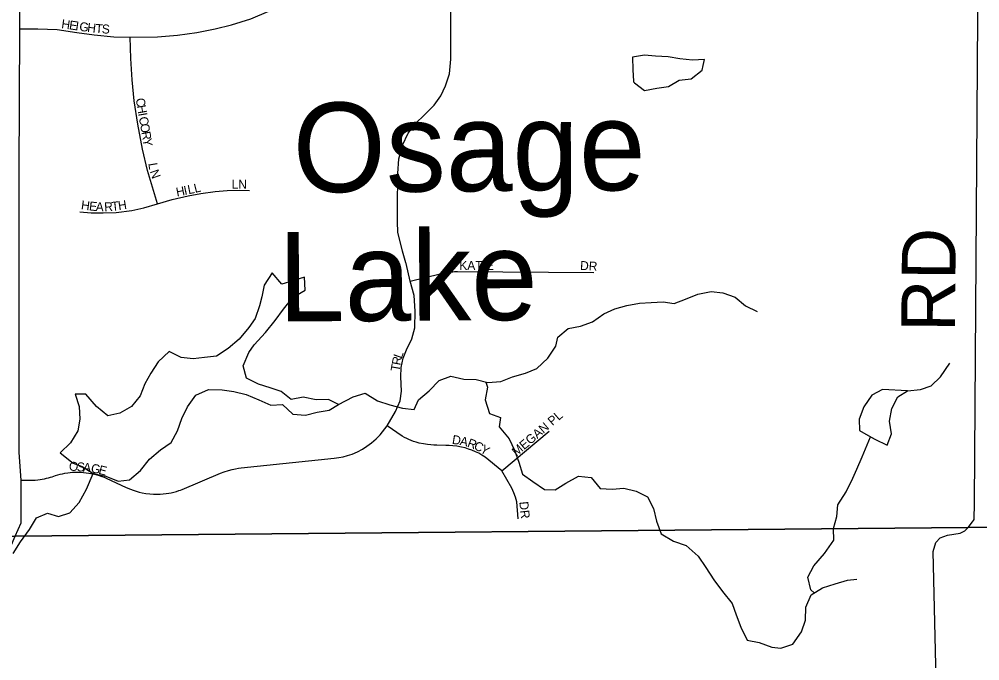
# Model space of a CAD drawing. Extents: x 1985906 to 2277390, y 930619 to 1324581.
# Drawn here: x 2168137 to 2173502, y 1115597 to 1119183 of the extents above; entities that cross this region are included whole.
import ezdxf

# ---------------------------------------------------------------- set-up
doc = ezdxf.new("R2010")
doc.units = 0
for name, color, linetype in [('GM_X_Minor_Lake', 7, 'Continuous'), ('GM_X_Minor_Lake_Text', 7, 'Continuous'), ('GM_X_Minor_River', 7, 'Continuous'), ('GM_X_Township', 7, 'Continuous'), ('GM_X_Township_Road', 7, 'Continuous'), ('GM_X_Township_Road_Text', 7, 'Continuous'), ('GM_X_Township_Subdivision', 7, 'Continuous'), ('GM_X_Township_Subdivision_Text', 7, 'Continuous')]:
    doc.layers.add(name, color=color, linetype=linetype)

msp = doc.modelspace()

# ---------------------------------------------------------------- linework, layer by layer
at = {"layer": 'GM_X_Minor_Lake'}
for points in [[(2171957.9, 1118923.5), (2171965.3, 1118956.9), (2171897.3, 1118953.6), (2171827, 1118962.3), (2171762.7, 1118973.1), (2171690.6, 1118975.8), (2171630.4, 1118982.7), (2171562.5, 1118971.4), (2171563.8, 1118899.3), (2171568, 1118835.9)], [(2171957.9, 1118923.5), (2171965.3, 1118956.9), (2171897.3, 1118953.6), (2171827, 1118962.3), (2171762.7, 1118973.1), (2171690.6, 1118975.8), (2171630.4, 1118982.7), (2171562.5, 1118971.4), (2171563.8, 1118899.3), (2171568, 1118835.8)], [(2171568, 1118835.9), (2171569.1, 1118832.8), (2171573.2, 1118827.4), (2171630.1, 1118784.4), (2171697.9, 1118797.7), (2171763.8, 1118806.9), (2171823.2, 1118842.1), (2171891.2, 1118849.3), (2171952.4, 1118898.6), (2171957.9, 1118923.5)], [(2171568.1, 1118835.8), (2171569.1, 1118832.8), (2171573.2, 1118827.4), (2171630.1, 1118784.4), (2171697.9, 1118797.7), (2171763.8, 1118806.9), (2171823.2, 1118842.1), (2171891.2, 1118849.3), (2171952.4, 1118898.6), (2171957.9, 1118923.5)], [(2169420.5, 1117319), (2169449.7, 1117363.6), (2169512.5, 1117430.9), (2169567.3, 1117498), (2169614.2, 1117563), (2169667, 1117630.1), (2169734.4, 1117667.4), (2169731, 1117741.4), (2169665.3, 1117720.2), (2169603.6, 1117701), (2169550.3, 1117766.1), (2169505.5, 1117697.2), (2169492.7, 1117630.8), (2169479.6, 1117580.5), (2169454.9, 1117509.9), (2169419.8, 1117459.2), (2169365, 1117394.1), (2169303.9, 1117342.9), (2169238.6, 1117299.6), (2169172.6, 1117292.3), (2169108.7, 1117285.1), (2169042.5, 1117291.9), (2168973.8, 1117324.7), (2168912.7, 1117267.5), (2168871.9, 1117204.6), (2168839, 1117143.9), (2168812.2, 1117077.3), (2168765.2, 1117018.3), (2168699.8, 1116981.1), (2168632, 1116965.8), (2168568.9, 1117018.7), (2168509.6, 1117087.7), (2168449.5, 1117086.6), (2168472.8, 1117018.9), (2168476.1, 1116946.8), (2168465.3, 1116882.6), (2168424.5, 1116815.7), (2168365.5, 1116758.5), (2168438.7, 1116701.8), (2168489.1, 1116682.7), (2168547.6, 1116645.2)], [(2169420.5, 1117319), (2169449.7, 1117363.6), (2169512.5, 1117430.9), (2169567.3, 1117498), (2169614.2, 1117563), (2169667, 1117630.1), (2169734.4, 1117667.4), (2169731, 1117741.4), (2169665.3, 1117720.2), (2169603.6, 1117701), (2169550.3, 1117766.1), (2169505.5, 1117697.2), (2169492.7, 1117630.8), (2169479.6, 1117580.5), (2169454.9, 1117509.9), (2169419.8, 1117459.2), (2169365, 1117394.1), (2169303.9, 1117342.9), (2169238.6, 1117299.6), (2169172.6, 1117292.3), (2169108.7, 1117285.1), (2169042.5, 1117291.9), (2168973.8, 1117324.7), (2168912.7, 1117267.5), (2168871.9, 1117204.6), (2168839, 1117143.9), (2168812.2, 1117077.3), (2168765.2, 1117018.3), (2168699.8, 1116981.1), (2168632, 1116965.8), (2168568.9, 1117018.7), (2168509.6, 1117087.7), (2168449.5, 1117086.6), (2168472.8, 1117018.9), (2168476.1, 1116946.8), (2168465.3, 1116882.6), (2168424.5, 1116815.7), (2168365.5, 1116758.5), (2168438.7, 1116701.8), (2168489.1, 1116682.7), (2168549.9, 1116643.8)], [(2168547.6, 1116645.2), (2168557.6, 1116642.6), (2168620.3, 1116629.1), (2168688.9, 1116600.3), (2168752.9, 1116607.5), (2168814, 1116660.7), (2168864.9, 1116723.8), (2168926, 1116775), (2168985.3, 1116816.1), (2169022.1, 1116882.9), (2169044.8, 1116951.4), (2169077.7, 1117016.1), (2169124.5, 1117081.1), (2169194, 1117112.5), (2169270.1, 1117111.9), (2169336.4, 1117101.1), (2169404.8, 1117084.3), (2169475.5, 1117055.6), (2169542.1, 1117024.8), (2169608.1, 1117030.1), (2169665.2, 1116975), (2169735.4, 1116970.3), (2169801.2, 1116985.6), (2169869.1, 1116996.9), (2169920.6, 1117029.9), (2169864, 1117056.8), (2169795.9, 1117055.6), (2169723.5, 1117070.3), (2169655.7, 1117057), (2169600.8, 1117102), (2169538.3, 1117122.9), (2169473.8, 1117143.7), (2169407.1, 1117176.5), (2169387.8, 1117246.3), (2169420.5, 1117319)], [(2168550.1, 1116644.6), (2168557.6, 1116642.6), (2168620.3, 1116629.1), (2168688.9, 1116600.3), (2168752.9, 1116607.5), (2168814, 1116660.7), (2168864.9, 1116723.8), (2168926, 1116775), (2168985.3, 1116816.1), (2169022.1, 1116882.9), (2169044.8, 1116951.4), (2169077.7, 1117016.1), (2169124.5, 1117081.1), (2169194, 1117112.5), (2169270.1, 1117111.9), (2169336.4, 1117101.1), (2169404.8, 1117084.3), (2169475.5, 1117055.6), (2169542.1, 1117024.8), (2169608.1, 1117030.1), (2169665.2, 1116975), (2169735.4, 1116970.3), (2169801.2, 1116985.6), (2169869.1, 1116996.9), (2169920.6, 1117029.9), (2169864, 1117056.8), (2169795.9, 1117055.6), (2169723.5, 1117070.3), (2169655.7, 1117057), (2169600.8, 1117102), (2169538.3, 1117122.9), (2169473.8, 1117143.7), (2169407.1, 1117176.5), (2169387.8, 1117246.3), (2169420.5, 1117319)], [(2173099.3, 1117105.2), (2172959.2, 1117112.6), (2172899.7, 1117081.4), (2172854.8, 1117016.5), (2172828.1, 1116947.9), (2172831.3, 1116883.8), (2172869.3, 1116861.9)], [(2173099.5, 1117105.2), (2172959.2, 1117112.6), (2172899.7, 1117081.4), (2172854.8, 1117016.5), (2172828.1, 1116947.9), (2172831.3, 1116883.8), (2172891.2, 1116849.3)], [(2172869.3, 1116861.9), (2172916.3, 1116835.3), (2172985, 1116802.6), (2173009.9, 1116865.1), (2172998.5, 1116937), (2173011.2, 1117007.4), (2173044, 1117072.1), (2173099.3, 1117105.2)], [(2172891.6, 1116849.3), (2172916.3, 1116835.3), (2172985, 1116802.6), (2173009.9, 1116865.1), (2172998.5, 1116937), (2173011.2, 1117007.4), (2173044, 1117072.1), (2173099.5, 1117105.3)]]:
    msp.add_lwpolyline(points, dxfattribs=at)
at = {"layer": 'GM_X_Minor_River'}
for points in [[(2169920.5, 1117029.9), (2170001.9, 1117071.4), (2170069.6, 1117092.7), (2170138.5, 1117050), (2170207, 1117027.2), (2170277.5, 1117008.5), (2170343.7, 1117001.7), (2170366.7, 1117056.2), (2170427.8, 1117105.4), (2170482.9, 1117162.5), (2170548.5, 1117187.8), (2170620.9, 1117171.1), (2170689, 1117168.4), (2170755.4, 1117151.6), (2170827.4, 1117156.9), (2170893, 1117184.2), (2170964.7, 1117203.6), (2171028.3, 1117230.8), (2171089.3, 1117288), (2171134.1, 1117354.9), (2171145.2, 1117405.2), (2171202.4, 1117454.4), (2171272.2, 1117467.7), (2171339.9, 1117491), (2171403.1, 1117536.2), (2171464.7, 1117563.4), (2171530.4, 1117582.7), (2171602.3, 1117596), (2171666.3, 1117599.2), (2171734.3, 1117602.5), (2171794.6, 1117593.6), (2171858.2, 1117618.8), (2171927.8, 1117646.2), (2172001.6, 1117661.6), (2172067.8, 1117652.8), (2172136.4, 1117630), (2172193.3, 1117581), (2172258.1, 1117548.2)], [(2173099.5, 1117105.2), (2173171.5, 1117112.5), (2173231.1, 1117133.6), (2173282.3, 1117184.7), (2173334.9, 1117259.8)], [(2170744.2, 1117154.4), (2170751.9, 1117125.5), (2170739.2, 1117055.1), (2170764.7, 1116979.5), (2170825.2, 1116956.6), (2170818.1, 1116904.4), (2170873.5, 1116837.3), (2170902.7, 1116773.8), (2170928, 1116706.1), (2170947.3, 1116640.4), (2171006.1, 1116599.4), (2171071, 1116554.6), (2171131.2, 1116551.7), (2171190.6, 1116588.8), (2171261.9, 1116628.2), (2171332.1, 1116621.5), (2171381.4, 1116560.4), (2171449.5, 1116555.6), (2171513.5, 1116560.8), (2171583.9, 1116544.1), (2171646.6, 1116513.2), (2171679.9, 1116447.8), (2171697.2, 1116378), (2171722.6, 1116306.3), (2171791.4, 1116265.6), (2171862, 1116240.8), (2171929.2, 1116182), (2171972.4, 1116118.7), (2172017.8, 1116049.4), (2172065.1, 1115984.2), (2172118.4, 1115917.1), (2172141.6, 1115853.5), (2172167, 1115783.8), (2172202.4, 1115712.4), (2172270.7, 1115699.6), (2172341.3, 1115672.9), (2172391.5, 1115667.8), (2172459.1, 1115689.1), (2172505.9, 1115758.1), (2172528.7, 1115824.6), (2172531.4, 1115896.8), (2172560.1, 1115965.4), (2172623.5, 1116004.6), (2172695.2, 1116026), (2172762.8, 1116047.3), (2172814.8, 1116052.3)], [(2172578.2, 1115976.6), (2172559.6, 1115993.4), (2172542.3, 1116063.2), (2172575.1, 1116127.9), (2172635.9, 1116197.2), (2172686.6, 1116270.2), (2172685.3, 1116336.3), (2172704.1, 1116402.8), (2172708.9, 1116468.9), (2172755.6, 1116541.9), (2172794.2, 1116616.8), (2172815.3, 1116667.2), (2172846.1, 1116735.9), (2172892.1, 1116848.8)], [(2168103.7, 1116196.8), (2168144.5, 1116261.6), (2168195.3, 1116330.7), (2168234.1, 1116395.5), (2168295.7, 1116422.7), (2168356.1, 1116403.8), (2168419.9, 1116423), (2168472.8, 1116482.1), (2168513.5, 1116556.9), (2168549.5, 1116644.1)]]:
    msp.add_lwpolyline(points, dxfattribs=at)
at = {"layer": 'GM_X_Township'}
for points in [[(2192559.7, 1126775.7), (2192552.2, 1123393.2), (2192551.5, 1123337.2), (2192556.7, 1120002.2), (2192568.4, 1119398.8), (2192561.7, 1116842), (2192562.2, 1116521.2), (2190954.5, 1116506.1), (2185162.6, 1116451.9), (2181245.1, 1116415.3), (2179282, 1116396.9), (2173437.9, 1116342.2), (2168114, 1116292.4), (2165645.9, 1116289.6), (2165645.2, 1116532.9), (2165622.7, 1122079.9), (2165632.9, 1123203.2), (2165639.1, 1129787.2)], [(2165679.9, 1110362.3), (2165650.7, 1113722.2), (2165646.2, 1113909.7), (2165645.9, 1116289.6), (2168114, 1116292.4), (2173437.9, 1116342.2), (2179282, 1116396.9), (2181245.1, 1116415.3), (2185162.6, 1116451.9), (2190954.5, 1116506.1)]]:
    msp.add_lwpolyline(points, dxfattribs=at)
at = {"layer": 'GM_X_Township_Road'}
for points in [[(2168064.4, 1115847.3), (2168074.1, 1115881.8), (2168064, 1115985.9), (2168065.8, 1116136), (2168087.7, 1116232.1), (2168114, 1116292.4), (2168148.3, 1116367.6), (2168148.3, 1116606.2), (2168137.3, 1116760.4), (2168137.3, 1118328.1), (2168140.3, 1119128.8), (2168144.2, 1120142.6), (2168144.2, 1121453.2), (2168138.9, 1123211.9)], [(2173466.4, 1116380.4), (2173470.5, 1116385.9), (2173472.4, 1116477.9), (2173500.6, 1120554.7), (2173487.4, 1121879.7), (2173494.2, 1123208.8)], [(2173302, 1113669.3), (2173242.8, 1116207.5), (2173256.8, 1116257.5), (2173280.7, 1116283.6), (2173322.7, 1116299.6), (2173392.6, 1116309.7), (2173419.5, 1116324), (2173437.9, 1116342.2), (2173461.5, 1116373.8), (2173466.4, 1116380.4)]]:
    msp.add_lwpolyline(points, dxfattribs=at)
at = {"layer": 'GM_X_Township_Subdivision'}
for points in [[(2168140.3, 1119128.8), (2168240.4, 1119129), (2168348.5, 1119125.1), (2168459.7, 1119109.1), (2168555.4, 1119095.2), (2168666.1, 1119084.9), (2168757.2, 1119081.9), (2168908.6, 1119083.8), (2169020.5, 1119093.3), (2169128.8, 1119108.5), (2169232.5, 1119128.8), (2169323.5, 1119151.4), (2169431.2, 1119184.1), (2169532.2, 1119227.5), (2169614.7, 1119258.2), (2169695, 1119288.3), (2169738.1, 1119299.8), (2169790.9, 1119308.4), (2169845.9, 1119311.4), (2170133.7, 1119311), (2170548.5, 1119310.4)], [(2170296.5, 1117821.2), (2170278.5, 1117886.9), (2170252.5, 1117992.2), (2170249.8, 1118051), (2170249.8, 1118127.6), (2170252.2, 1118319.8), (2170257.2, 1118401.8), (2170277.7, 1118479), (2170310.2, 1118545.8), (2170350.1, 1118600.4), (2170400.1, 1118648.7), (2170454.9, 1118702.7), (2170491.5, 1118754.4), (2170519, 1118809.8), (2170539.7, 1118878.1), (2170548, 1118958.8), (2170548.5, 1119310.4)], [(2168909.6, 1118150.6), (2168854.2, 1118338), (2168825.8, 1118456.5), (2168798.8, 1118596.6), (2168779.9, 1118726), (2168767.6, 1118844.7), (2168760.1, 1118962.4), (2168757.2, 1119081.9)], [(2168474.8, 1118107), (2168538.6, 1118101.4), (2168605.3, 1118099.8), (2168678.7, 1118103.3), (2168765.7, 1118114.5), (2168832.7, 1118128.5), (2168909.6, 1118150.6), (2168992.3, 1118175.4), (2169081.2, 1118196.4), (2169150.7, 1118208.9), (2169231.4, 1118219.3), (2169298.2, 1118224.5), (2169368.5, 1118226.7), (2169423.8, 1118226.2)], [(2168148.3, 1116606.2), (2168197.9, 1116606.2), (2168211.9, 1116606.4), (2168225.9, 1116607.2), (2168240.9, 1116608.5), (2168254.4, 1116610.2), (2168266.1, 1116612), (2168278.4, 1116614.3), (2168290.2, 1116617), (2168300.7, 1116619.6), (2168311.7, 1116622.7), (2168320.9, 1116625.5), (2168330.1, 1116628.6), (2168340.7, 1116632.1), (2168353.6, 1116636), (2168366.4, 1116639.4), (2168379, 1116642.3), (2168392.2, 1116644.9), (2168407.8, 1116647.3), (2168421.7, 1116649), (2168434.9, 1116650.1), (2168447.8, 1116650.8), (2168460, 1116651), (2168472.7, 1116650.9), (2168483.7, 1116650.5), (2168496.4, 1116649.6), (2168511.6, 1116648), (2168525.6, 1116646), (2168538, 1116643.8), (2168551.1, 1116641.1), (2168565.8, 1116637.4), (2168583.7, 1116632.2), (2168599.5, 1116626.8), (2168610.7, 1116622.5), (2168623.6, 1116617), (2168734.7, 1116565.3), (2168758.4, 1116555.1), (2168773.3, 1116549.6), (2168790, 1116544.3), (2168807, 1116539.6), (2168823, 1116536), (2168843.8, 1116532.2), (2168866.9, 1116529.4), (2168887.1, 1116528), (2168905.8, 1116527.7), (2168924.1, 1116528.2), (2168941.2, 1116529.5), (2168957.2, 1116531.3), (2168972.2, 1116533.6), (2168986.3, 1116536.3), (2169000.6, 1116539.6), (2169015.6, 1116543.6), (2169029, 1116547.7), (2169038.2, 1116550.9), (2169047.4, 1116554.3), (2169260.6, 1116644.7), (2169281.8, 1116653), (2169305.2, 1116660.6), (2169325.9, 1116666), (2169345.4, 1116670), (2169361.6, 1116672.7), (2169376.6, 1116674.4), (2169896.4, 1116728.9), (2169921.6, 1116732.4), (2169946.7, 1116737.5), (2169969.9, 1116743.7), (2169995.9, 1116752.5), (2170026, 1116765.3), (2170053.8, 1116779.8), (2170079.5, 1116795.9), (2170104.3, 1116814.1), (2170131.4, 1116837.8), (2170152.4, 1116859.5), (2170193.2, 1116910.9), (2170238.2, 1116990.5), (2170264.4, 1117049), (2170272.1, 1117104.5), (2170269, 1117183), (2170270.5, 1117235.3), (2170281.3, 1117287.7), (2170299.8, 1117333.9), (2170330.6, 1117395.5), (2170347.5, 1117457.1), (2170349.1, 1117551), (2170342.9, 1117638.8), (2170321.7, 1117718.6), (2170297.6, 1117817.1), (2170296.5, 1117821.2)], [(2170321.7, 1117718.6), (2170488.1, 1117759.3), (2170495.1, 1117761.1), (2170502.4, 1117762.9), (2170509.7, 1117764.5), (2170517.5, 1117766), (2170526.3, 1117767.6), (2170535.3, 1117769), (2170543.3, 1117770), (2170552.3, 1117771), (2170558.9, 1117771.6), (2170569.2, 1117772.3), (2170577.5, 1117772.7), (2170585.2, 1117772.9), (2171346, 1117766.4)], [(2170923.8, 1116389.6), (2170915.9, 1116485.1), (2170908.9, 1116511), (2170900.7, 1116535), (2170889.5, 1116561.7), (2170832, 1116657.6), (2170740.4, 1116735.1), (2170721.5, 1116746.7), (2170703.5, 1116756.6), (2170685.3, 1116765.4), (2170665.6, 1116773.6), (2170646.4, 1116780.5), (2170628.2, 1116786.1), (2170606.6, 1116791.4), (2170581, 1116796.2), (2170559.9, 1116798.8), (2170538.3, 1116800.4), (2170520.1, 1116800.8), (2170470.1, 1116801.7), (2170452.8, 1116802), (2170437.1, 1116802.9), (2170417.3, 1116805), (2170394.8, 1116808.6), (2170371, 1116813.8), (2170354.7, 1116818.3), (2170339, 1116823.3), (2170325.6, 1116828.2), (2170313.5, 1116833.1), (2170301.3, 1116838.4), (2170288.6, 1116844.6), (2170275.2, 1116851.6), (2170193.2, 1116910.9)], [(2170832, 1116657.6), (2171097.8, 1116880.5)]]:
    msp.add_lwpolyline(points, dxfattribs=at)

# ---------------------------------------------------------------- texts
at = {"layer": 'GM_X_Minor_Lake_Text'}
for s, rotation, p in [('Osage ', 0.3593, (2169666.3, 1118215.1)), (' Lake', 0.3595, (2169398.2, 1117492))]:
    msp.add_text(s, height=500.2, rotation=rotation, dxfattribs=at).set_placement(p)
at = {"layer": 'GM_X_Township_Road_Text'}
msp.add_text('RD', height=300, rotation=89.5063, dxfattribs=at).set_placement((2173363.7, 1117435.2))
at = {"layer": 'GM_X_Township_Subdivision_Text'}
for s, rotation, p in [('H', 351.907, (2168370.2, 1119133)), ('E', 351.9096, (2168413.7, 1119126.8)), ('I', 351.8884, (2168448.6, 1119121.9)), ('G', 351.9198, (2168470.4, 1119118.8)), ('H', 352.9044, (2168514.9, 1119112.5)), ('T', 356.1773, (2168561.7, 1119106.7)), ('S', 356.7969, (2168597.4, 1119104.3)), ('C', 279.7378, (2168787.3, 1118738.1)), ('H', 279.7282, (2168794, 1118699.1)), ('I', 279.7629, (2168801.4, 1118655.7)), ('C', 279.7378, (2168805.2, 1118634)), ('O', 279.7282, (2168811.9, 1118595)), ('R', 279.7471, (2168819.3, 1118551.6)), ('Y', 279.5737, (2168826, 1118512.6)), ('L', 279.2198, (2168857.8, 1118376.1)), ('N', 289.3123, (2168865.8, 1118332.2)), ('H', 11.4428, (2169018.3, 1118191.2)), ('I', 11.4699, (2169061.4, 1118199.9)), ('L', 11.4439, (2169083, 1118204.3)), ('L', 13.7516, (2169119.6, 1118211.7)), ('LN', 0, (2169323.6, 1118235.4)), ('H', 352.2624, (2168480.2, 1118120.9)), ('E', 354.0208, (2168525.5, 1118114.7)), ('A', 357.0881, (2168563.4, 1118110.8)), ('R', 3.3662, (2168613.3, 1118108.6)), ('T', 6.2462, (2168655.6, 1118111.2)), ('H', 9.0277, (2168693.2, 1118115.4)), ('KATIE', 0, (2170595.2, 1117781.7)), ('DR', 356.8222, (2171268.9, 1117781.7)), ('R', 79.1282, (2170266.3, 1117245.7)), ('L', 70.9343, (2170273.2, 1117282.7)), ('T', 80.2547, (2170260.3, 1117211.2)), ('MEGAN PL', 40.4265, (2170914.7, 1116737.3)), ('D', 351.1126, (2170552.4, 1116809.9)), ('A', 347.9571, (2170595.1, 1116803.2)), ('R', 339.1455, (2170636.2, 1116794.6)), ('C', 336.2816, (2170672.6, 1116780.8)), ('Y', 328.6689, (2170707.3, 1116765.7)), ('O', 355.8209, (2168413.5, 1116660.3)), ('S', 355.848, (2168457.4, 1116657.1)), ('A', 354.7462, (2168492.2, 1116654.6)), ('G', 348.4671, (2168534.6, 1116650.8)), ('E', 345.7849, (2168577.1, 1116642.1)), ('DR', 276.0054, (2170930.2, 1116484.7))]:
    msp.add_text(s, height=50, rotation=rotation, dxfattribs=at).set_placement(p)

doc.saveas('drawing.dxf')
